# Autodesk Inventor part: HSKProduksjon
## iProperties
Created: 2009-12
Part Number: HSKProduksjon
Document SubType Name: Modeling
Designer: a31733
Density: 1 g/cm^3
Author: a31733
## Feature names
1. Circular Pattern1
2. Extrusion1
3. Loft1
4. Extrusion2
5. Extrusion4
6. Revolution1
7. Fillet5
8. Fillet6
9. Extrusion5
10. Fillet7
11. Extrusion6
12. Extrusion7
13. Circular Pattern2
